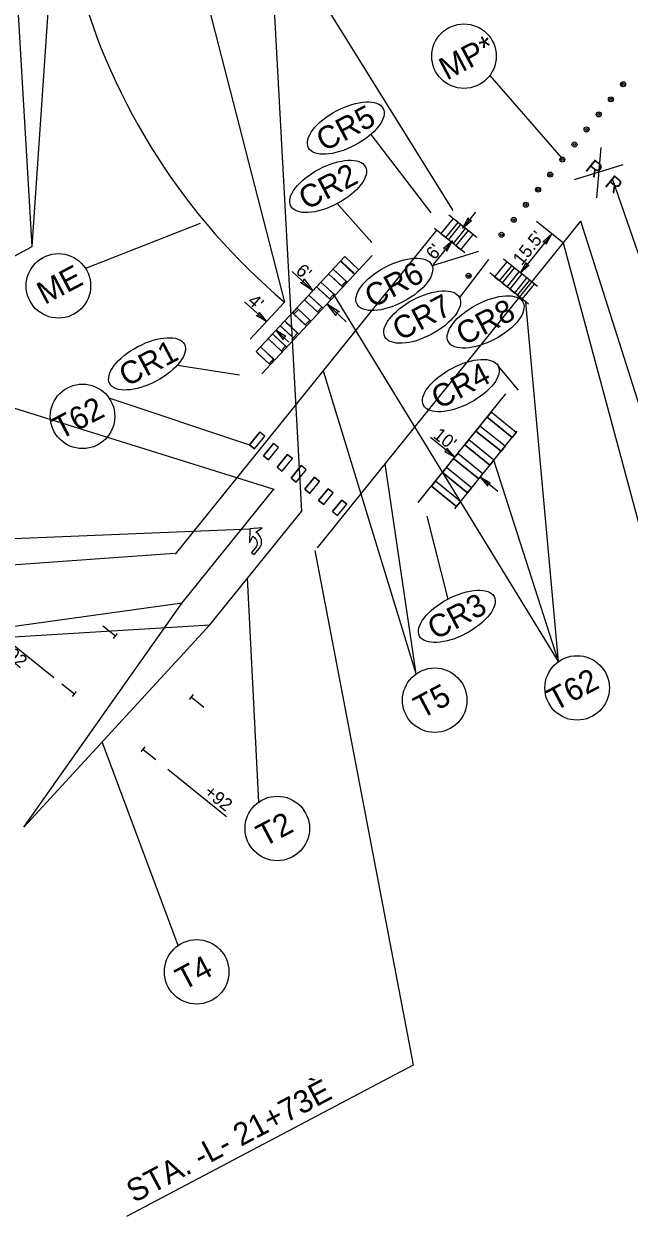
# Model space of a CAD drawing. Extents: x 1487421 to 1489048, y 497792 to 499463.
# Drawn here: x 1488599.3 to 1488787, y 498825.6 to 499195.5 of the extents above; entities that cross this region are included whole.
import ezdxf

# ---------------------------------------------------------------- set-up
doc = ezdxf.new("R2010")
doc.units = 0
for name, color, linetype in [('DEV TUBULAR MARKER PLAN VIEW CELL', 7, 'Continuous'), ('MARK LEFT TURN ARROW CELL', 7, 'Continuous'), ('MARK RAILROAD SYMBOL CELL', 7, 'Continuous'), ('Prop Dimension', 7, 'Continuous'), ('Prop Dimension Text', 7, 'Continuous'), ('Prop Mkg 3ft Min Skp 9ft White', 7, 'Continuous'), ('Prop Mkg Min Skp 6ft White', 7, 'Continuous'), ('Prop Mkg Solid Dbl Yel Rpm 80ft', 7, 'Continuous'), ('Prop Mkg Solid White Crosswalks', 7, 'Continuous'), ('Prop Mkg Solid White Lane Line', 7, 'Continuous'), ('Prop Mkg Solid White Stop Bar', 7, 'Continuous'), ('Scratch_Level_3', 7, 'Continuous'), ('Scratch_Level_5', 7, 'Continuous'), ('Text', 7, 'Continuous')]:
    doc.layers.add(name, color=color, linetype=linetype)

msp = doc.modelspace()

# ---------------------------------------------------------------- linework, layer by layer
at = {"layer": 'DEV TUBULAR MARKER PLAN VIEW CELL'}
for centre, radius in [((1488785.12, 499176.72), 0.781), ((1488785.12, 499176.72), 0.332), ((1488781.35, 499172.05), 0.781), ((1488781.35, 499172.05), 0.332), ((1488777.58, 499167.38), 0.781), ((1488777.58, 499167.38), 0.332), ((1488773.82, 499162.71), 0.781), ((1488773.82, 499162.71), 0.332), ((1488770.05, 499158.04), 0.781), ((1488770.05, 499158.04), 0.332), ((1488766.28, 499153.37), 0.781), ((1488766.28, 499153.37), 0.332), ((1488762.52, 499148.7), 0.781), ((1488762.52, 499148.7), 0.332), ((1488758.75, 499144.03), 0.781), ((1488758.75, 499144.03), 0.332), ((1488754.98, 499139.36), 0.781), ((1488754.98, 499139.36), 0.332), ((1488751.22, 499134.69), 0.781), ((1488751.22, 499134.69), 0.332), ((1488747.45, 499130.02), 0.781), ((1488747.45, 499130.02), 0.332), ((1488737.21, 499117.32), 0.781), ((1488737.21, 499117.32), 0.332)]:
    msp.add_circle(centre, radius, dxfattribs=at)
at = {"layer": 'MARK LEFT TURN ARROW CELL'}
for points in [[(1488669.94, 499031.47), (1488670.72, 499030.85), (1488672.34, 499032.86), (1488672.62, 499033.25), (1488672.8, 499033.57), (1488672.95, 499033.95), (1488673.02, 499034.32), (1488673.04, 499034.62), (1488673.03, 499035.06), (1488672.97, 499035.39), (1488672.89, 499035.76), (1488672.73, 499036.19), (1488672.56, 499036.49), (1488672.31, 499036.85), (1488671.91, 499037.28), (1488671.28, 499037.78), (1488673.21, 499039.11), (1488669.38, 499038.88), (1488669.26, 499034.48), (1488670.29, 499036.55), (1488670.8, 499036.13), (1488671.08, 499035.88), (1488671.29, 499035.59), (1488671.42, 499035.32), (1488671.56, 499034.95), (1488671.63, 499034.65), (1488671.63, 499034.23), (1488671.54, 499033.81), (1488671.41, 499033.43), (1488671.14, 499032.97)], [(1488669.94, 499031.47), (1488670.72, 499030.85), (1488672.34, 499032.86), (1488672.62, 499033.25), (1488672.8, 499033.57), (1488672.95, 499033.95), (1488673.02, 499034.32), (1488673.04, 499034.62), (1488673.03, 499035.06), (1488672.97, 499035.39), (1488672.89, 499035.76), (1488672.73, 499036.19), (1488672.56, 499036.49), (1488672.31, 499036.85), (1488671.91, 499037.28), (1488671.28, 499037.78), (1488673.21, 499039.11), (1488669.38, 499038.88), (1488669.26, 499034.48), (1488670.28, 499036.55), (1488670.8, 499036.13), (1488671.08, 499035.88), (1488671.29, 499035.59), (1488671.42, 499035.32), (1488671.56, 499034.95), (1488671.63, 499034.65), (1488671.63, 499034.23), (1488671.54, 499033.81), (1488671.41, 499033.43), (1488671.14, 499032.97)]]:
    msp.add_lwpolyline(points, close=True, dxfattribs=at)
at = {"layer": 'MARK RAILROAD SYMBOL CELL'}
for p, q in [((1488778.27, 499157.15), (1488776.91, 499141.47)), ((1488785.04, 499151.69), (1488770, 499147.04))]:
    msp.add_line(p, q, dxfattribs=at)
at = {"layer": 'Prop Dimension'}
for p, q in [((1488739.33, 499137.03), (1488735.34, 499132.08)), ((1488732.2, 499128.19), (1488726.25, 499120.8)), ((1488763.03, 499130.3), (1488753.3, 499118.24)), ((1488682.51, 499118.7), (1488688.94, 499112.7)), ((1488667.76, 499109.19), (1488674.51, 499103.09)), ((1488693.33, 499108.61), (1488699.26, 499103.08)), ((1488677.47, 499100.41), (1488681.51, 499096.76)), ((1488732.98, 499061.09), (1488725.42, 499067.18)), ((1488746.27, 499050.37), (1488740.76, 499054.81)), ((1488594.27, 499004.33), (1488608.59, 498992.77)), ((1488643.91, 498964.3), (1488662.16, 498949.57))]:
    msp.add_line(p, q, dxfattribs=at)
for points in [[(1488737.11, 499135.27), (1488735.34, 499132.08), (1488738.1, 499134.5), (1488737.32, 499134.54)], [(1488730.44, 499124.98), (1488732.2, 499128.19), (1488729.44, 499125.75), (1488730.23, 499125.71)], [(1488761.25, 499127.11), (1488763.03, 499130.3), (1488760.26, 499127.89), (1488761.05, 499127.84)], [(1488756.04, 499120.65), (1488753.3, 499118.24), (1488755.07, 499121.46), (1488755.28, 499120.7)], [(1488686.18, 499116.34), (1488688.94, 499112.7), (1488685.09, 499115.21), (1488686.06, 499115.4)], [(1488672.25, 499105.96), (1488674.51, 499103.09), (1488671.39, 499105.04), (1488672.16, 499105.21)], [(1488696.08, 499104.97), (1488693.33, 499108.61), (1488697.18, 499106.1), (1488696.21, 499105.91)], [(1488680.56, 499098.45), (1488677.47, 499100.41), (1488679.73, 499097.5), (1488679.82, 499098.29)], [(1488729.75, 499062.81), (1488732.98, 499061.09), (1488730.51, 499063.81), (1488730.48, 499063.03)], [(1488743.95, 499053.03), (1488740.76, 499054.81), (1488743.17, 499052.04), (1488743.21, 499052.82)]]:
    msp.add_lwpolyline(points, close=True, dxfattribs=at)
at = {"layer": 'Prop Mkg 3ft Min Skp 9ft White'}
msp.add_line((1488656.94, 499009.02), (1488599.3, 498946.31), dxfattribs=at)
at = {"layer": 'Prop Mkg Min Skp 6ft White'}
for p, q in [((1488646.37, 499030.96), (1488727.39, 499131.42)), ((1488690.38, 499032.96), (1488772.04, 499134.22))]:
    msp.add_line(p, q, dxfattribs=at)
at = {"layer": 'Prop Mkg Solid Dbl Yel Rpm 80ft'}
for p, q in [((1488648.38, 499015.93), (1488676.79, 499051.16)), ((1488599.3, 498946.31), (1488648.38, 499015.93))]:
    msp.add_line(p, q, dxfattribs=at)
msp.add_arc((1488809.02, 499262.12), 200, 195.2846, 229.8892, dxfattribs=at)
at = {"layer": 'Prop Mkg Solid White Crosswalks'}
for p, q in [((1488732.38, 499135.11), (1488728.61, 499130.44)), ((1488739.72, 499129.19), (1488731.09, 499136.15)), ((1488733.94, 499133.85), (1488732.38, 499135.11)), ((1488736.08, 499124.41), (1488726.67, 499132.01)), ((1488730.17, 499129.18), (1488733.94, 499133.85)), ((1488734.72, 499133.22), (1488730.95, 499128.55)), ((1488732.51, 499127.3), (1488736.27, 499131.97)), ((1488736.27, 499131.97), (1488734.72, 499133.22)), ((1488728.61, 499130.44), (1488730.17, 499129.18)), ((1488730.95, 499128.55), (1488732.51, 499127.3)), ((1488737.05, 499131.34), (1488733.28, 499126.67)), ((1488734.84, 499125.41), (1488738.61, 499130.08)), ((1488738.61, 499130.08), (1488737.05, 499131.34)), ((1488733.28, 499126.67), (1488734.84, 499125.41)), ((1488698.83, 499123.3), (1488671.31, 499093.8)), ((1488707.32, 499123.61), (1488673.07, 499086.88)), ((1488698.83, 499123.3), (1488697.46, 499121.84)), ((1488697.46, 499121.84), (1488701.85, 499117.75)), ((1488697.57, 499121.95), (1488701.96, 499117.86)), ((1488701.59, 499118.21), (1488698.3, 499121.27)), ((1488703.22, 499119.21), (1488698.83, 499123.3)), ((1488749.05, 499121.66), (1488745.29, 499116.99)), ((1488746.84, 499115.74), (1488750.61, 499120.41)), ((1488758.55, 499114.01), (1488748.01, 499122.5)), ((1488750.61, 499120.41), (1488749.05, 499121.66)), ((1488695.18, 499119.39), (1488693.82, 499117.93)), ((1488693.82, 499117.93), (1488698.21, 499113.84)), ((1488693.82, 499117.93), (1488698.21, 499113.84)), ((1488697.84, 499114.18), (1488694.5, 499117.3)), ((1488699.57, 499115.3), (1488695.18, 499119.39)), ((1488695.18, 499119.39), (1488699.57, 499115.3)), ((1488699.2, 499115.65), (1488695.88, 499118.74)), ((1488701.85, 499117.75), (1488703.22, 499119.21)), ((1488755.74, 499108.56), (1488743.79, 499118.2)), ((1488745.29, 499116.99), (1488746.84, 499115.74)), ((1488751.39, 499119.78), (1488747.62, 499115.11)), ((1488749.18, 499113.85), (1488752.94, 499118.52)), ((1488753.72, 499117.9), (1488749.96, 499113.22)), ((1488752.94, 499118.52), (1488751.39, 499119.78)), ((1488751.51, 499111.97), (1488755.28, 499116.64)), ((1488755.28, 499116.64), (1488753.72, 499117.9)), ((1488691.43, 499115.37), (1488690.07, 499113.91)), ((1488690.07, 499113.91), (1488694.45, 499109.82)), ((1488690.07, 499113.91), (1488694.45, 499109.82)), ((1488694.08, 499110.16), (1488690.69, 499113.32)), ((1488695.82, 499111.28), (1488691.43, 499115.37)), ((1488691.43, 499115.37), (1488695.82, 499111.28)), ((1488695.45, 499111.62), (1488692.08, 499114.77)), ((1488699.2, 499115.65), (1488697.84, 499114.18)), ((1488698.21, 499113.84), (1488699.57, 499115.3)), ((1488747.62, 499115.11), (1488749.18, 499113.85)), ((1488749.96, 499113.22), (1488751.51, 499111.97)), ((1488756.06, 499116.01), (1488752.29, 499111.34)), ((1488753.85, 499110.09), (1488757.61, 499114.76)), ((1488757.61, 499114.76), (1488756.06, 499116.01)), ((1488687.68, 499111.35), (1488686.32, 499109.89)), ((1488686.32, 499109.89), (1488690.7, 499105.79)), ((1488686.32, 499109.89), (1488690.7, 499105.79)), ((1488690.33, 499106.14), (1488686.89, 499109.35)), ((1488692.07, 499107.26), (1488687.68, 499111.35)), ((1488687.68, 499111.35), (1488692.07, 499107.26)), ((1488691.7, 499107.6), (1488688.27, 499110.8)), ((1488695.45, 499111.62), (1488694.08, 499110.16)), ((1488694.45, 499109.82), (1488695.82, 499111.28)), ((1488752.29, 499111.34), (1488753.85, 499110.09)), ((1488683.93, 499107.33), (1488682.56, 499105.86)), ((1488682.56, 499105.86), (1488686.95, 499101.77)), ((1488682.56, 499105.86), (1488686.95, 499101.77)), ((1488684.46, 499106.83), (1488683.07, 499105.39)), ((1488688.32, 499103.23), (1488683.93, 499107.33)), ((1488683.93, 499107.33), (1488688.32, 499103.23)), ((1488687.95, 499103.58), (1488684.46, 499106.83)), ((1488691.7, 499107.6), (1488690.33, 499106.14)), ((1488690.7, 499105.79), (1488692.07, 499107.26)), ((1488680.18, 499103.3), (1488678.81, 499101.84)), ((1488678.81, 499101.84), (1488683.2, 499097.75)), ((1488678.81, 499101.84), (1488683.2, 499097.75)), ((1488684.56, 499099.21), (1488680.18, 499103.3)), ((1488680.18, 499103.3), (1488684.56, 499099.21)), ((1488684.2, 499099.56), (1488680.66, 499102.85)), ((1488686.58, 499102.12), (1488683.07, 499105.39)), ((1488687.95, 499103.58), (1488686.58, 499102.12)), ((1488686.95, 499101.77), (1488688.32, 499103.23)), ((1488676.43, 499099.28), (1488675.06, 499097.82)), ((1488680.81, 499095.19), (1488676.43, 499099.28)), ((1488676.43, 499099.28), (1488680.81, 499095.19)), ((1488680.44, 499095.53), (1488676.86, 499098.88)), ((1488682.83, 499098.09), (1488679.28, 499101.41)), ((1488682.83, 499098.09), (1488684.2, 499099.56)), ((1488683.2, 499097.75), (1488684.56, 499099.21)), ((1488672.67, 499095.26), (1488671.31, 499093.8)), ((1488677.06, 499091.17), (1488672.67, 499095.26)), ((1488672.67, 499095.26), (1488677.06, 499091.17)), ((1488676.69, 499091.51), (1488673.06, 499094.9)), ((1488675.06, 499097.82), (1488679.45, 499093.73)), ((1488675.06, 499097.82), (1488679.45, 499093.73)), ((1488679.08, 499094.07), (1488675.48, 499097.43)), ((1488680.44, 499095.53), (1488679.08, 499094.07)), ((1488679.45, 499093.73), (1488680.81, 499095.19)), ((1488671.31, 499093.8), (1488675.7, 499089.71)), ((1488671.31, 499093.8), (1488675.7, 499089.71)), ((1488675.33, 499090.05), (1488671.67, 499093.46)), ((1488676.69, 499091.51), (1488675.33, 499090.05)), ((1488675.7, 499089.71), (1488677.06, 499091.17)), ((1488721.57, 499046.95), (1488748.81, 499080.72)), ((1488742.93, 499073.44), (1488744.19, 499075)), ((1488744.19, 499075), (1488742.93, 499073.44)), ((1488750.72, 499067.16), (1488742.93, 499073.44)), ((1488742.93, 499073.44), (1488750.72, 499067.16)), ((1488751.97, 499068.72), (1488744.19, 499075)), ((1488751.97, 499068.72), (1488744.19, 499075)), ((1488732.91, 499045.08), (1488752.29, 499069.11)), ((1488739.48, 499069.16), (1488740.74, 499070.72)), ((1488740.74, 499070.72), (1488739.48, 499069.16)), ((1488747.27, 499062.88), (1488739.48, 499069.16)), ((1488739.48, 499069.16), (1488747.27, 499062.88)), ((1488748.52, 499064.44), (1488740.74, 499070.72)), ((1488748.52, 499064.44), (1488740.74, 499070.72)), ((1488751.97, 499068.72), (1488750.72, 499067.16)), ((1488750.72, 499067.16), (1488751.97, 499068.72)), ((1488737.29, 499066.44), (1488736.03, 499064.88)), ((1488737.29, 499066.44), (1488736.03, 499064.88)), ((1488743.81, 499058.6), (1488736.03, 499064.88)), ((1488736.03, 499064.88), (1488743.81, 499058.6)), ((1488745.07, 499060.16), (1488737.29, 499066.44)), ((1488745.07, 499060.16), (1488737.29, 499066.44)), ((1488732.58, 499060.6), (1488733.83, 499062.15)), ((1488733.83, 499062.15), (1488732.58, 499060.6)), ((1488741.62, 499055.88), (1488733.83, 499062.15)), ((1488741.62, 499055.88), (1488733.83, 499062.15)), ((1488748.52, 499064.44), (1488747.27, 499062.88)), ((1488747.27, 499062.88), (1488748.52, 499064.44)), ((1488730.38, 499057.87), (1488729.12, 499056.32)), ((1488730.38, 499057.87), (1488729.12, 499056.32)), ((1488738.16, 499051.6), (1488730.38, 499057.87)), ((1488738.16, 499051.6), (1488730.38, 499057.87)), ((1488740.36, 499054.32), (1488732.58, 499060.6)), ((1488732.58, 499060.6), (1488740.36, 499054.32)), ((1488745.07, 499060.16), (1488743.81, 499058.6)), ((1488743.81, 499058.6), (1488745.07, 499060.16)), ((1488736.91, 499050.04), (1488729.12, 499056.32)), ((1488729.12, 499056.32), (1488736.91, 499050.04)), ((1488740.36, 499054.32), (1488741.62, 499055.88)), ((1488740.36, 499054.32), (1488741.62, 499055.88)), ((1488726.93, 499053.59), (1488725.67, 499052.04)), ((1488726.93, 499053.59), (1488725.67, 499052.04)), ((1488733.46, 499045.76), (1488725.67, 499052.04)), ((1488725.67, 499052.04), (1488733.46, 499045.76)), ((1488734.71, 499047.31), (1488726.93, 499053.59)), ((1488734.71, 499047.31), (1488726.93, 499053.59)), ((1488738.16, 499051.6), (1488736.91, 499050.04)), ((1488736.91, 499050.04), (1488738.16, 499051.6)), ((1488734.71, 499047.31), (1488733.46, 499045.76)), ((1488733.46, 499045.76), (1488734.71, 499047.31))]:
    msp.add_line(p, q, dxfattribs=at)
at = {"layer": 'Prop Mkg Solid White Lane Line'}
for p, q in [((1488656.94, 499009.02), (1488685.35, 499044.25)), ((1488623.8, 499008.77), (1488627.69, 499005.64)), ((1488627.06, 499004.86), (1488628.32, 499006.41)), ((1488611.1, 498990.76), (1488614.99, 498987.62)), ((1488614.36, 498986.84), (1488615.62, 498988.4)), ((1488650.64, 498985.85), (1488651.89, 498987.4)), ((1488651.26, 498986.63), (1488655.16, 498983.49)), ((1488635.72, 498969.62), (1488636.97, 498971.17)), ((1488636.35, 498970.39), (1488640.24, 498967.26))]:
    msp.add_line(p, q, dxfattribs=at)
at = {"layer": 'Prop Mkg Solid White Stop Bar'}
for p, q in [((1488766.64, 499127.39), (1488758.24, 499134.16)), ((1488680.17, 499109.16), (1488669.48, 499097.7))]:
    msp.add_line(p, q, dxfattribs=at)
at = {"layer": 'Scratch_Level_3'}
for p, q in [((1488625.68, 499079.47), (1488669.31, 499064.9)), ((1488669.31, 499064.9), (1488672.45, 499068.79)), ((1488672.45, 499068.79), (1488669.31, 499064.9)), ((1488674.01, 499067.53), (1488672.45, 499068.79)), ((1488674.01, 499067.53), (1488672.45, 499068.79)), ((1488670.87, 499063.64), (1488669.31, 499064.9)), ((1488669.31, 499064.9), (1488670.87, 499063.64)), ((1488670.87, 499063.64), (1488674.01, 499067.53)), ((1488670.87, 499063.64), (1488674.01, 499067.53)), ((1488673.59, 499061.45), (1488676.73, 499065.34)), ((1488676.73, 499065.34), (1488673.59, 499061.45)), ((1488678.29, 499064.08), (1488676.73, 499065.34)), ((1488678.29, 499064.08), (1488676.73, 499065.34)), ((1488675.15, 499060.19), (1488673.59, 499061.45)), ((1488673.59, 499061.45), (1488675.15, 499060.19)), ((1488675.15, 499060.19), (1488678.29, 499064.08)), ((1488675.15, 499060.19), (1488678.29, 499064.08)), ((1488677.88, 499057.99), (1488681.01, 499061.88)), ((1488681.01, 499061.88), (1488677.88, 499057.99)), ((1488681.01, 499061.89), (1488682.57, 499060.63)), ((1488682.57, 499060.63), (1488681.01, 499061.88)), ((1488677.88, 499057.99), (1488679.43, 499056.74)), ((1488677.88, 499057.99), (1488679.43, 499056.74)), ((1488679.43, 499056.74), (1488682.57, 499060.63)), ((1488679.43, 499056.74), (1488682.57, 499060.63)), ((1488682.16, 499054.54), (1488685.29, 499058.43)), ((1488685.29, 499058.43), (1488682.16, 499054.54)), ((1488686.85, 499057.18), (1488685.29, 499058.43)), ((1488686.85, 499057.18), (1488685.29, 499058.43)), ((1488683.71, 499053.29), (1488682.16, 499054.54)), ((1488682.16, 499054.54), (1488683.71, 499053.29)), ((1488683.71, 499053.29), (1488686.85, 499057.18)), ((1488683.71, 499053.29), (1488686.85, 499057.18)), ((1488686.44, 499051.09), (1488689.45, 499054.82)), ((1488689.45, 499054.82), (1488686.44, 499051.09)), ((1488689.45, 499054.82), (1488690.98, 499053.53)), ((1488690.98, 499053.53), (1488689.45, 499054.82)), ((1488687.99, 499049.83), (1488686.44, 499051.09)), ((1488686.44, 499051.09), (1488687.99, 499049.83)), ((1488687.99, 499049.83), (1488690.98, 499053.53)), ((1488687.99, 499049.83), (1488690.98, 499053.53)), ((1488690.72, 499047.64), (1488693.66, 499051.29)), ((1488693.66, 499051.29), (1488690.72, 499047.64)), ((1488693.66, 499051.29), (1488695.2, 499050)), ((1488695.2, 499050), (1488693.66, 499051.29)), ((1488692.28, 499046.38), (1488690.72, 499047.64)), ((1488690.72, 499047.64), (1488692.28, 499046.38)), ((1488692.28, 499046.38), (1488695.2, 499050)), ((1488692.28, 499046.38), (1488695.2, 499050)), ((1488695, 499044.18), (1488697.88, 499047.76)), ((1488697.88, 499047.76), (1488695, 499044.18)), ((1488696.56, 499042.93), (1488699.42, 499046.48)), ((1488696.56, 499042.93), (1488699.42, 499046.48)), ((1488697.88, 499047.76), (1488699.42, 499046.48)), ((1488699.42, 499046.48), (1488697.88, 499047.76)), ((1488695, 499044.18), (1488696.56, 499042.93))]:
    msp.add_line(p, q, dxfattribs=at)
msp.add_circle((1488617.5, 499073.71), 10, dxfattribs=at)
at = {"layer": 'Scratch_Level_5'}
msp.add_line((1488725.67, 499052.04), (1488744.19, 499075), dxfattribs=at)
at = {"layer": 'Text'}
for p, q in [((1488674.91, 499237.45), (1488685.35, 499044.25)), ((1488601.93, 499126.36), (1488609.09, 499231.88)), ((1488648.19, 499233.22), (1488680.17, 499109.16)), ((1488601.93, 499126.36), (1488595.88, 499227.25)), ((1488683.08, 499216.92), (1488732.3, 499137.52)), ((1488743.8, 499179.46), (1488765.92, 499154.06)), ((1488706.85, 499161.12), (1488725.53, 499136.87)), ((1488822.39, 499029.61), (1488781.98, 499147.09)), ((1488707.22, 499127.64), (1488696.49, 499139.69)), ((1488653.95, 499133.58), (1488618.45, 499119.56)), ((1488822.74, 498974.13), (1488772.04, 499134.22)), ((1488512.71, 499079.25), (1488601.93, 499126.36)), ((1488740.28, 499124.88), (1488725.91, 499120.39)), ((1488811.22, 498961.61), (1488766.64, 499127.39)), ((1488743.38, 499122.38), (1488734.39, 499110.61)), ((1488765.1, 498997.66), (1488695.44, 499111.54)), ((1488765.1, 498997.66), (1488755.01, 499109.15)), ((1488646.93, 499089.63), (1488666.13, 499086.56)), ((1488720.95, 498993.85), (1488692.18, 499087.77)), ((1488752.71, 499081.82), (1488746.38, 499089.36)), ((1488576.94, 499082.31), (1488676.79, 499051.16)), ((1488720.95, 498993.85), (1488711.38, 499059.01)), ((1488765.1, 498997.66), (1488745.07, 499060.16)), ((1488724.29, 499042.79), (1488730.74, 499017.04)), ((1488403.63, 499028), (1488669.38, 499038.88)), ((1488720.08, 498872.55), (1488689.66, 499032.07)), ((1488532.23, 499023.09), (1488645.98, 499031.28)), ((1488672.12, 498954.07), (1488668.7, 499023.61)), ((1488554.22, 499002.72), (1488648.38, 499015.93)), ((1488554.22, 499002.72), (1488656.94, 499009.02)), ((1488647.13, 498909.59), (1488623.57, 498972.72)), ((1488631.24, 498825.65), (1488720.08, 498872.55))]:
    msp.add_line(p, q, dxfattribs=at)
for centre in [(1488735.78, 499185.44), (1488610.02, 499114.19), (1488770.86, 498989.49), (1488726.71, 498985.67), (1488677.88, 498945.9), (1488652.89, 498901.42)]:
    msp.add_circle(centre, 10, dxfattribs=at)
for centre in [(1488699.12, 499163.14), (1488693.66, 499145.05), (1488714.18, 499114.65), (1488722.82, 499104.5), (1488742.5, 499103), (1488637.5, 499090), (1488734.81, 499083.25), (1488733.57, 499011.69)]:
    msp.add_ellipse(centre, major_axis=(11.57, 6.11), ratio=0.462467, dxfattribs=at)

# ---------------------------------------------------------------- texts
at = {"layer": 'MARK RAILROAD SYMBOL CELL'}
msp.add_text('R  R', height=4.556, rotation=321.1156, dxfattribs=at).set_placement((1488773.1, 499150.21))
at = {"layer": 'Prop Dimension'}
for s, rotation, p in [("15.5'", 51.1156, (1488753.67, 499120.26)), ("6'", 51.1156, (1488726.71, 499122.03)), ("6'", 318.5306, (1488683.35, 499118.44)), ("4'", 318.5306, (1488668.45, 499109.06)), ("10'", 322.2334, (1488725.96, 499067.34))]:
    msp.add_text(s, height=4, rotation=rotation, dxfattribs=at).set_placement(p)
at = {"layer": 'Prop Dimension Text'}
for p in [(1488591.24, 499001.13), (1488654.88, 498956.64)]:
    msp.add_text('+92', height=4, rotation=321.1156, dxfattribs=at).set_placement(p)
at = {"layer": 'Scratch_Level_3'}
msp.add_text('T62', height=7, rotation=27.835, dxfattribs=at).set_placement((1488610.62, 499066.38))
at = {"layer": 'Text'}
for s, rotation, p in [('MP*', 27.8351, (1488730.47, 499177.85)), ('CR5', 27.8351, (1488692.39, 499155.7)), ('CR2', 27.8351, (1488686.93, 499137.59)), ('ME', 27.835, (1488605.78, 499108.26)), ('CR6', 27.8351, (1488707.38, 499107.16)), ('CR7', 27.8351, (1488716, 499097)), ('CR8', 27.8351, (1488735.72, 499095.52)), ('CR1', 27.8351, (1488631.21, 499082.78)), ('CR4', 27.8351, (1488728.06, 499075.79)), ('CR3', 27.8351, (1488726.87, 499004.26)), ('T62', 27.835, (1488763.98, 498982.16)), ('T5', 27.835, (1488722.62, 498979.82)), ('T2', 27.835, (1488673.78, 498940.04)), ('T4', 27.835, (1488648.77, 498895.55)), ('STA. -L- 21+73È', 27.835, (1488633.49, 498829.64))]:
    msp.add_text(s, height=7, rotation=rotation, dxfattribs=at).set_placement(p)

doc.saveas('drawing.dxf')
